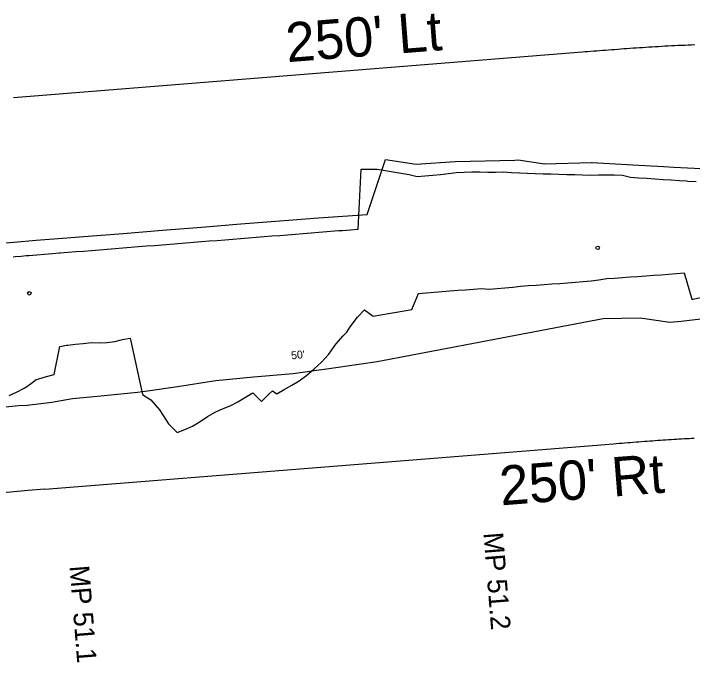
# Model space of a CAD drawing. Extents: x 7860037 to 7875910, y 598622 to 603049.
# Drawn here: x 7870460 to 7871323, y 602219 to 603045 of the extents above; entities that cross this region are included whole.
import ezdxf

# ---------------------------------------------------------------- set-up
doc = ezdxf.new("R2010")
doc.units = 0
for name, color, linetype in [('Level 11', 7, 'Continuous'), ('Level 15', 7, 'Continuous'), ('Level 16', 7, 'Continuous'), ('Level 24', 7, 'Continuous'), ('P_RW_EASE_Perm', 7, 'Continuous')]:
    doc.layers.add(name, color=color, linetype=linetype)

msp = doc.modelspace()

# ---------------------------------------------------------------- linework, layer by layer
at = {"layer": 'Level 11'}
for centre in [(7871202.57, 602746.62), (7870479.72, 602688.78)]:
    msp.add_circle(centre, 2.25, dxfattribs=at)
at = {"layer": 'Level 16'}
for points in [[(7870459.21, 602735.37), (7870461.82, 602735.59), (7870469.26, 602736.2), (7870475.89, 602736.73), (7870479.29, 602737), (7870489.26, 602737.8), (7870499.22, 602738.59), (7870509.19, 602739.38), (7870517.76, 602740.07), (7870519.16, 602740.18), (7870529.13, 602740.98), (7870539.1, 602741.77), (7870549.07, 602742.57), (7870559.03, 602743.36), (7870569, 602744.16), (7870578.97, 602744.97), (7870588.94, 602745.77), (7870598.91, 602746.57), (7870608.87, 602747.36), (7870618.84, 602748.16), (7870628.81, 602748.96), (7870638.78, 602749.75), (7870648.75, 602750.55), (7870658.72, 602751.34), (7870668.68, 602752.14), (7870678.65, 602752.94), (7870688.62, 602753.73), (7870698.59, 602754.53), (7870708.56, 602755.32), (7870718.52, 602756.12), (7870728.49, 602756.92), (7870738.46, 602757.71), (7870748.43, 602758.51), (7870758.4, 602759.31), (7870768.37, 602760.1), (7870773.35, 602760.5), (7870778.33, 602760.89), (7870788.3, 602761.69), (7870798.27, 602762.48), (7870808.24, 602763.28), (7870818.21, 602764.08), (7870828.18, 602764.87), (7870838.14, 602765.67), (7870848.11, 602766.47), (7870858.08, 602767.26), (7870868.05, 602768.05), (7870873.03, 602768.45), (7870878.02, 602768.85), (7870887.99, 602769.64), (7870897.95, 602770.44), (7870901.87, 602846.82), (7870911.91, 602846.79), (7870921.96, 602846.56), (7870932.12, 602845), (7870942.29, 602843.19), (7870952.47, 602841.42), (7870962.64, 602839.68), (7870972.87, 602837.23), (7870982.83, 602838.09), (7870992.79, 602838.95), (7871002.74, 602840.06), (7871012.68, 602841.17), (7871022.62, 602842.27), (7871032.61, 602842.85), (7871042.6, 602843.31), (7871052.64, 602843.22), (7871062.69, 602843.06), (7871072.72, 602843), (7871082.75, 602843.1), (7871092.83, 602842.43), (7871102.9, 602841.95), (7871112.96, 602841.62), (7871123.03, 602841.21), (7871133.1, 602840.72), (7871143.13, 602840.66), (7871153.19, 602840.39), (7871163.25, 602840.06), (7871173.3, 602839.74), (7871183.36, 602839.41), (7871193.42, 602839.12), (7871203.44, 602839.38), (7871213.52, 602839.64), (7871223.66, 602839.58), (7871233.88, 602839.02), (7871244.29, 602836.47), (7871254.59, 602835.83), (7871264.93, 602835.16), (7871275.3, 602834.46), (7871285.71, 602833.71), (7871296.14, 602832.93), (7871306.6, 602832.26), (7871315.42, 602831.68), (7871317.08, 602831.58), (7871327.58, 602831.03)], [(7870454.23, 602558.85), (7870463.68, 602563.12), (7870473.1, 602567.96), (7870475.54, 602569.21), (7870482.38, 602574.55), (7870488.49, 602579.21), (7870491.83, 602580.18), (7870501.64, 602583.04), (7870511.47, 602585.48), (7870518.65, 602621.23), (7870527.14, 602622.71), (7870528.54, 602622.96), (7870538.48, 602624.11), (7870548.46, 602624.78), (7870558.37, 602626.33), (7870568.44, 602625.86), (7870578.44, 602626.17), (7870588.37, 602627.53), (7870598.19, 602630.14), (7870608.08, 602631.85), (7870623.87, 602559.98), (7870634.44, 602553.25), (7870645.47, 602540.69), (7870656.94, 602522.76), (7870667.87, 602511.57), (7870677.59, 602515.45), (7870687.26, 602519.97), (7870696.83, 602525.77), (7870706.37, 602531.9), (7870715.95, 602537.59), (7870725.64, 602541.83), (7870735.36, 602545.75), (7870745, 602550.56), (7870754.53, 602556.82), (7870764.14, 602562.12), (7870775.04, 602551.35), (7870784.33, 602560.57), (7870789, 602564.93), (7870794.33, 602560.99), (7870803.92, 602566.47), (7870813.51, 602571.96), (7870823.11, 602577.44), (7870832.56, 602584.71), (7870841.95, 602592.65), (7870851.3, 602601.27), (7870860.52, 602611.41), (7870869.54, 602624.05), (7870878.72, 602634.68), (7870883.36, 602639.34), (7870887.83, 602646.27), (7870896.89, 602658.4), (7870906.18, 602667.62), (7870916.86, 602659.55), (7870926.75, 602661.27), (7870936.65, 602662.99), (7870946.55, 602664.58), (7870956.44, 602666.34), (7870966.34, 602668.08), (7870974.73, 602688.57), (7870984.69, 602689.4), (7870994.66, 602690.21), (7871004.63, 602691.02), (7871014.6, 602691.83), (7871024.56, 602692.63), (7871034.53, 602693.38), (7871044.51, 602694.11), (7871054.48, 602694.83), (7871064.57, 602694.19), (7871074.54, 602694.88), (7871084.51, 602695.66), (7871094.46, 602696.7), (7871104.4, 602697.82), (7871114.38, 602698.52), (7871124.36, 602699.22), (7871134.33, 602699.93), (7871144.3, 602700.67), (7871154.28, 602701.39), (7871164.25, 602702.12), (7871174.22, 602702.95), (7871184.18, 602703.76), (7871194.13, 602704.78), (7871204.09, 602705.75), (7871213.98, 602707.48), (7871223.92, 602708.19), (7871233.85, 602708.91), (7871243.76, 602709.63), (7871253.65, 602710.33), (7871263.52, 602711.03), (7871273.36, 602711.74), (7871283.19, 602712.45), (7871293, 602713.18), (7871302.79, 602713.91), (7871312.56, 602714.64)], [(7871312.56, 602714.64), (7871322.32, 602681.48), (7871323.84, 602681.41), (7871333.32, 602683.3), (7871342.89, 602682.23), (7871351.52, 602716.06)]]:
    msp.add_lwpolyline(points, dxfattribs=at)
at = {"layer": 'Level 24'}
for points in [[(7870847.31, 602784.87), (7870909.33, 602789.03), (7870932.79, 602858.75), (7870971.55, 602853.14), (7871021.37, 602856.32), (7871097.29, 602858.03), (7871101.2, 602858.62), (7871135.05, 602853.24), (7871194.75, 602854.97), (7871195.63, 602855.01), (7871247.36, 602852.34), (7871286.31, 602850.23), (7871299.24, 602849.41), (7871351.39, 602846.62), (7871404.98, 602844.76), (7871459.93, 602838.83), (7871515.33, 602828.97), (7871569.41, 602813.11), (7871570.17, 602812.87), (7871622.63, 602793.28), (7871670.04, 602771.92)], [(7869947.79, 602688.52), (7869997.66, 602696.93), (7870047.61, 602704.91), (7870097.62, 602712.45), (7870147.7, 602719.55), (7870197.84, 602726.22), (7870248.04, 602732.45), (7870298.28, 602738.24), (7870348.58, 602743.59), (7870398.92, 602748.5), (7870449.27, 602752.97), (7870460.32, 602753.89), (7870488.37, 602756.16), (7870499.43, 602757.04), (7870516.29, 602758.39), (7870549.27, 602761.03), (7870599.11, 602765.02), (7870648.95, 602769), (7870698.79, 602772.99), (7870748.63, 602776.98), (7870798.47, 602780.97), (7870847.31, 602784.87)], [(7870630.18, 602564.78), (7870668.32, 602570.03), (7870716.86, 602577.9), (7870764.65, 602582.57), (7870815.5, 602586.68), (7870866.69, 602593.8), (7870922.26, 602601.9), (7871209.32, 602656.63)], [(7871209.32, 602656.63), (7871256.41, 602657.71), (7871294.21, 602651.89), (7871308.86, 602653.33), (7871355.19, 602658.98), (7871399.67, 602658.74), (7871444.42, 602654.51), (7871488.91, 602651.14), (7871532.21, 602647.02), (7871534.44, 602646.74), (7871579, 602652.24), (7871614.63, 602636.47), (7871654.21, 602616.07), (7871695.27, 602596.26), (7871735.32, 602578.18), (7871768.24, 602551.12), (7871756.9, 602495.72)], [(7869813.1, 602439.69), (7869818.14, 602440.14), (7869840.55, 602443.5), (7869887.32, 602452.26), (7869935.57, 602456.55), (7869990.43, 602464.9), (7870039.12, 602482.46), (7870081.84, 602492.29), (7870127.97, 602498.33), (7870175.67, 602504.17), (7870226.54, 602508.6), (7870276.86, 602518.67), (7870323.68, 602526.69), (7870372.45, 602533.01), (7870420.52, 602541.24), (7870466.15, 602546.15), (7870477.25, 602546.56), (7870508.43, 602550.36), (7870520.29, 602552.53), (7870534.88, 602554.86), (7870566.42, 602557.82), (7870617.25, 602563), (7870630.18, 602564.78)]]:
    msp.add_lwpolyline(points, dxfattribs=at)
at = {"layer": 'P_RW_EASE_Perm'}
for p, q in [((7870459.79, 602937.99), (7871182.63, 602995.82)), ((7870499.66, 602439.58), (7871222.51, 602497.41))]:
    msp.add_line(p, q, dxfattribs=at)
for points in [[(7871182.64, 602995.82), (7871186.32, 602996.12), (7871190.02, 602996.41), (7871193.73, 602996.71), (7871197.46, 602997.01), (7871201.21, 602997.3), (7871204.98, 602997.6), (7871208.76, 602997.9), (7871212.56, 602998.19), (7871216.38, 602998.49), (7871220.21, 602998.79), (7871224.06, 602999.08), (7871227.93, 602999.37), (7871231.81, 602999.66), (7871235.71, 602999.95), (7871239.63, 603000.23), (7871243.57, 603000.52), (7871247.52, 603000.8), (7871251.49, 603001.07), (7871255.48, 603001.35), (7871259.49, 603001.61), (7871263.51, 603001.88), (7871267.55, 603002.14), (7871271.61, 603002.39), (7871275.68, 603002.64), (7871279.77, 603002.89), (7871283.88, 603003.12), (7871288.01, 603003.36), (7871292.15, 603003.58), (7871296.31, 603003.8), (7871300.49, 603004.01), (7871304.68, 603004.21), (7871308.9, 603004.41), (7871313.13, 603004.59), (7871317.37, 603004.77), (7871321.64, 603004.94), (7871325.92, 603005.1)], [(7871222.51, 602497.41), (7871226.17, 602497.71), (7871229.82, 602498), (7871233.45, 602498.29), (7871237.06, 602498.58), (7871240.66, 602498.86), (7871244.24, 602499.14), (7871247.8, 602499.42), (7871251.35, 602499.7), (7871254.88, 602499.97), (7871258.39, 602500.25), (7871261.89, 602500.51), (7871265.37, 602500.77), (7871268.83, 602501.03), (7871272.28, 602501.29), (7871275.71, 602501.54), (7871279.12, 602501.78), (7871282.52, 602502.02), (7871285.9, 602502.26), (7871289.26, 602502.49), (7871292.61, 602502.71), (7871295.94, 602502.93), (7871299.25, 602503.14), (7871302.55, 602503.35), (7871305.83, 602503.55), (7871309.09, 602503.75), (7871312.34, 602503.93), (7871315.57, 602504.12), (7871318.79, 602504.29), (7871321.98, 602504.46), (7871325.16, 602504.62)]]:
    msp.add_lwpolyline(points, dxfattribs=at)
msp.add_arc((7870936.68, 596977.46), 5479.58, 94.57443, 101.88023, dxfattribs=at)

# ---------------------------------------------------------------- texts
at = {"layer": 'Level 15'}
for s, p in [('MP 51.2', (7871057.19, 602383.87)), ('MP 51.1', (7870530.87, 602341.76))]:
    msp.add_text(s, height=25, rotation=274.57443, dxfattribs=at).set_placement(p)
at = {"layer": 'Level 24'}
msp.add_text("50'", height=10, rotation=6.50647, dxfattribs=at).set_placement((7870813.24, 602604.61))
at = {"layer": 'P_RW_EASE_Perm'}
for s, p in [("250' Lt", (7870807.82, 602982.68)), ("250' Rt", (7871079.61, 602418.96))]:
    msp.add_text(s, height=50, rotation=4.46716, dxfattribs=at).set_placement(p)

doc.saveas('drawing.dxf')
